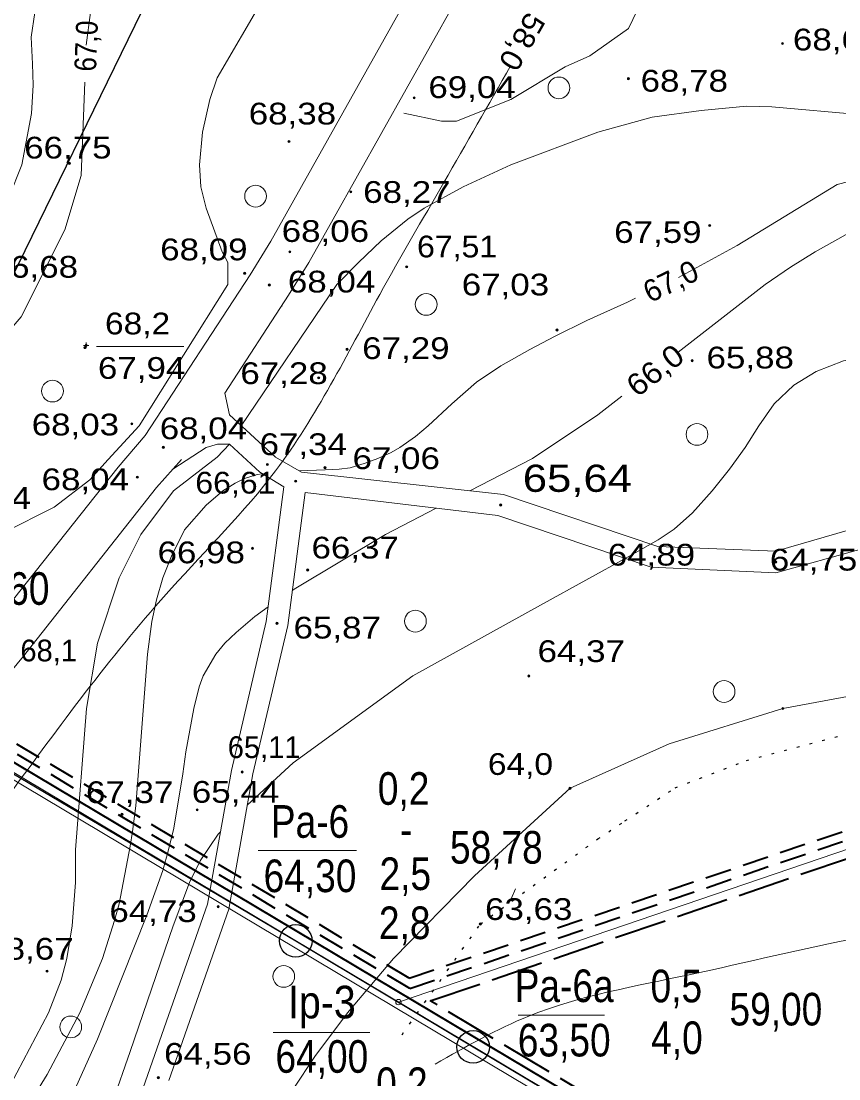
# Model space of a CAD drawing. Extents: x 628176 to 629009, y 6439913 to 6440496.
# Drawn here: x 628286 to 628361.2, y 6440164.9 to 6440262.2 of the extents above; entities that cross this region are included whole.
import ezdxf
from ezdxf.enums import TextEntityAlignment as Align

# ---------------------------------------------------------------- set-up
doc = ezdxf.new("R2010")
doc.units = 0
doc.header["$LTSCALE"] = 0.8
for name, pattern in [('DOTTED', [1.5, 0.3, -1.2]), ('LONG_DASHED', [7.5, 6, -1.5]), ('MEDIUM_DASHED', [4.5, 3, -1.5])]:
    doc.linetypes.add(name, pattern=pattern)
for name, color, linetype, lineweight in [('1', 7, 'Continuous', 13), ('11', 7, 'Continuous', 13), ('12', 7, 'Continuous', 13), ('14', 7, 'Continuous', 25), ('16', 7, 'Continuous', 13), ('21', 7, 'MEDIUM_DASHED', 35), ('3', 7, 'Continuous', 13), ('6', 7, 'Continuous', 13)]:
    doc.layers.add(name, color=color, linetype=linetype, lineweight=lineweight)

msp = doc.modelspace()

# ---------------------------------------------------------------- hatches: boundary and pattern name
at = {"layer": '1'}
for points in [[(628356.0743, 6440260.1483, 1), (628355.8743, 6440260.1483, 1)], [(628341.9107, 6440256.9194, 1), (628341.7107, 6440256.9194, 1)], [(628322.2211, 6440255.1543, 1), (628322.0211, 6440255.1543, 1)], [(628310.7102, 6440251.1349, 1), (628310.5102, 6440251.1349, 1)], [(628290.5201, 6440249.1263, 1), (628290.3201, 6440249.1263, 1)], [(628316.3947, 6440246.5031, 1), (628316.1947, 6440246.5031, 1)], [(628349.3792, 6440243.4059, 1), (628349.1792, 6440243.4059, 1)], [(628310.7867, 6440240.9912, 1), (628310.5867, 6440240.9912, 1)], [(628321.5289, 6440239.6149, 1), (628321.3289, 6440239.6149, 1)], [(628306.6381, 6440239.022, 1), (628306.4381, 6440239.022, 1)], [(628308.9023, 6440237.9449, 1), (628308.7023, 6440237.9449, 1)], [(628335.3481, 6440233.8017, 1), (628335.1481, 6440233.8017, 1)], [(628291.9429, 6440232.1859, 1), (628291.7429, 6440232.1859, 1)], [(628292.0618, 6440232.3913, 1), (628291.8618, 6440232.3913, 1)], [(628316.0509, 6440232.031, 1), (628315.8509, 6440232.031, 1)], [(628347.7719, 6440230.9816, 1), (628347.5719, 6440230.9816, 1)], [(628313.4424, 6440229.4082, 1), (628313.2424, 6440229.4082, 1)], [(628296.2665, 6440225.1736, 1), (628296.0665, 6440225.1736, 1)], [(628299.1586, 6440223.008, 1), (628298.9586, 6440223.008, 1)], [(628308.7274, 6440221.4346, 1), (628308.5274, 6440221.4346, 1)], [(628314.015, 6440221.1369, 1), (628313.815, 6440221.1369, 1)], [(628296.7687, 6440220.2651, 1), (628296.5687, 6440220.2651, 1)], [(628311.3292, 6440219.9008, 1), (628311.1292, 6440219.9008, 1)], [(628330.1709, 6440217.705, 1), (628329.9709, 6440217.705, 1)], [(628307.3536, 6440213.7223, 1), (628307.1536, 6440213.7223, 1)], [(628344.3043, 6440212.9299, 1), (628344.1043, 6440212.9299, 1)], [(628355.4645, 6440212.4726, 1), (628355.2645, 6440212.4726, 1)], [(628312.433, 6440211.7256, 1), (628312.233, 6440211.7256, 1)], [(628309.6075, 6440206.8223, 1), (628309.4075, 6440206.8223, 1)], [(628332.7532, 6440201.9901, 1), (628332.5532, 6440201.9901, 1)], [(628356.0999, 6440198.9999, 1), (628355.8999, 6440198.9999, 1)], [(628306.4084, 6440193.1498, 1), (628306.2084, 6440193.1498, 1)], [(628336.5375, 6440191.6623, 1), (628336.3375, 6440191.6623, 1)], [(628295.359, 6440189.2608, 1), (628295.159, 6440189.2608, 1)], [(628302.2659, 6440189.6821, 1), (628302.0659, 6440189.6821, 1)], [(628304.2013, 6440180.7755, 1), (628304.0013, 6440180.7755, 1)], [(628328.2942, 6440179.1745, 1), (628328.0942, 6440179.1745, 1)], [(628288.4747, 6440174.84, 1), (628288.2747, 6440174.84, 1)], [(628298.6987, 6440165.0565, 1), (628298.4987, 6440165.0565, 1)]]:
    msp.add_hatch(color=256, dxfattribs=at).paths.add_polyline_path(points)

# ---------------------------------------------------------------- linework, layer by layer
for p, q in [((628308.95, 6440241.98), (628322.23, 6440265.66)), ((628312.42, 6440240), (628325.84, 6440263.93)), ((628307.03, 6440238.88), (628308.95, 6440241.98)), ((628310.56, 6440237), (628312.42, 6440240)), ((628297.39, 6440224.11), (628307.03, 6440238.88)), ((628304.7, 6440228), (628310.56, 6440237)), ((628291.96, 6440232.39), (628291.71, 6440232.39)), ((628291.96, 6440232.39), (628291.96, 6440232.64)), ((628291.96, 6440232.39), (628292.21, 6440232.39)), ((628291.96, 6440232.39), (628291.96, 6440232.14)), ((628300.93, 6440232.27), (628292.93, 6440232.27)), ((628305.13, 6440226), (628304.7, 6440228)), ((628309.36, 6440222.11), (628305.13, 6440226)), ((628294.9, 6440221.2), (628297.39, 6440224.11)), ((628307.93, 6440220.72), (628305.13, 6440223.29)), ((628311.77, 6440220.74), (628309.36, 6440222.11)), ((628282.81, 6440205.93), (628294.9, 6440221.2)), ((628298.44, 6440219.33), (628300.73, 6440221.9)), ((628310.15, 6440219.38), (628307.93, 6440220.72)), ((628330.33, 6440218.67), (628311.77, 6440220.74)), ((628286.21, 6440203.81), (628298.44, 6440219.33)), ((628308.52, 6440207), (628310.15, 6440219.38)), ((628310.49, 6440206.64), (628312.09, 6440218.85)), ((628329.82, 6440216.74), (628312.09, 6440218.85)), ((628344.5, 6440213.88), (628330.33, 6440218.67)), ((628343.9, 6440211.98), (628329.82, 6440216.74)), ((628364, 6440215.96), (628355.36, 6440213.47)), ((628355.36, 6440213.47), (628344.5, 6440213.88)), ((628364.35, 6440213.99), (628355.36, 6440211.47)), ((628355.36, 6440211.47), (628343.9, 6440211.98)), ((628305.32, 6440193.3), (628308.52, 6440207)), ((628307.3, 6440193), (628310.49, 6440206.64)), ((628269.01, 6440183.06), (628286.21, 6440203.81)), ((628303.13, 6440181), (628305.32, 6440193.3)), ((628305.08, 6440180.55), (628307.3, 6440193)), ((628297.64, 6440165.34), (628303.13, 6440181)), ((628299.56, 6440164.78), (628305.08, 6440180.55)), ((628286.97, 6440135.42), (628297.64, 6440165.34))]:
    msp.add_line(p, q, dxfattribs=at)
msp.add_lwpolyline([(628305.13, 6440223.29), (628304.04, 6440223.29), (628303, 6440223), (628299.92, 6440221)], dxfattribs=at)
at = {"layer": '1', "linetype": 'DOTTED', "lineweight": 25}
for points in [[(628339, 6440187), (628341.49, 6440188.66), (628346.11, 6440191.7), (628352.66, 6440194.21), (628361.18, 6440196.45)], [(628321, 6440169), (628328.19, 6440179.17), (628339, 6440187)]]:
    msp.add_lwpolyline(points, dxfattribs=at)
at = {"layer": '1'}
for centre, radius in [((628355.9743, 6440260.1483), 0.1), ((628335.4179, 6440256.0666), 1), ((628341.8107, 6440256.9194), 0.1), ((628322.1211, 6440255.1543), 0.1), ((628310.6102, 6440251.1349), 0.1), ((628290.4201, 6440249.1263), 0.1), ((628307.5389, 6440246.1098), 1), ((628316.2947, 6440246.5031), 0.1), ((628349.2792, 6440243.4059), 0.1), ((628310.6867, 6440240.9912), 0.1), ((628321.4289, 6440239.6149), 0.1), ((628306.5381, 6440239.022), 0.1), ((628308.8023, 6440237.9449), 0.1), ((628323.2209, 6440236.1531), 1), ((628335.2481, 6440233.8017), 0.1), ((628291.8429, 6440232.1859), 0.1), ((628291.9618, 6440232.3913), 0.1), ((628315.9509, 6440232.031), 0.1), ((628347.6719, 6440230.9816), 0.1), ((628288.87, 6440228.1876), 1), ((628313.3424, 6440229.4082), 0.1), ((628296.1665, 6440225.1736), 0.1), ((628348.1128, 6440224.2049), 1), ((628299.0586, 6440223.008), 0.1), ((628308.6274, 6440221.4346), 0.1), ((628313.915, 6440221.1369), 0.1), ((628296.6687, 6440220.2651), 0.1), ((628311.2292, 6440219.9008), 0.1), ((628330.0709, 6440217.705), 0.1), ((628307.2536, 6440213.7223), 0.1), ((628344.2043, 6440212.9299), 0.1), ((628355.3645, 6440212.4726), 0.1), ((628312.333, 6440211.7256), 0.1), ((628322.2252, 6440207.0295), 1), ((628309.5075, 6440206.8223), 0.1), ((628332.6532, 6440201.9901), 0.1), ((628350.602, 6440200.5576), 1), ((628355.9999, 6440198.9999), 0.1), ((628306.3084, 6440193.1498), 0.1), ((628336.4375, 6440191.6623), 0.1), ((628295.259, 6440189.2608), 0.1), ((628302.1659, 6440189.6821), 0.1), ((628304.1013, 6440180.7755), 0.1), ((628328.1942, 6440179.1745), 0.1), ((628310.1267, 6440174.3603), 1), ((628288.3747, 6440174.84), 0.1), ((628290.5482, 6440169.7104), 1), ((628298.5987, 6440165.0565), 0.1)]:
    msp.add_circle(centre, radius, dxfattribs=at)
at = {"layer": '11'}
for points in [[(628497.5, 6440118.54), (628474.19, 6440080.39), (628272.25, 6440200.89), (628236.02, 6440221.83), (628393.19, 6440398.39)], [(628320.67, 6440172), (628398.18, 6440198.42), (628472.21, 6440157.1), (628497.5, 6440118.54)]]:
    msp.add_lwpolyline(points, dxfattribs=at)
at = {"layer": '12'}
for p, q in [((628307.79, 6440185.95), (628316.83, 6440185.95)), ((628331.66, 6440170.81), (628339.61, 6440170.81)), ((628309.16, 6440169.2), (628318.03, 6440169.2))]:
    msp.add_line(p, q, dxfattribs=at)
at = {"layer": '12', "lineweight": 25}
for centre in [(628311.2274, 6440177.6315), (628327.5332, 6440167.8785)]:
    msp.add_circle(centre, 1.5, dxfattribs=at)
at = {"layer": '12'}
msp.add_circle((628320.6692, 6440171.9974), 0.25, dxfattribs=at)
at = {"layer": '14'}
msp.add_line((628326.62, 6440323.6), (628267.86, 6440203.3), dxfattribs=at)
msp.add_lwpolyline([(628267.86, 6440203.3), (628311.23, 6440177.63), (628327.53, 6440167.88), (628373.06, 6440140.73), (628474.19, 6440080.39), (628476.16, 6440079.17)], dxfattribs=at)
at = {"layer": '16'}
msp.add_line((628331.42, 6440182.41), (628331.04, 6440181.48), dxfattribs=at)
for points in [[(628330.97, 6440258.09), (628324.85, 6440247.37), (628318.95, 6440237.06), (628309.38, 6440220.86), (628299.81, 6440210.06), (628285.32, 6440191.65)], [(628369.28, 6440179.01), (628363.18, 6440177.96), (628347.39, 6440174.51), (628332.71, 6440170.73), (628324.04, 6440166.29)]]:
    msp.add_spline(points, degree=3, dxfattribs=at)
at = {"layer": '21', "linetype": 'Continuous', "lineweight": 40}
for points in [[(628320.39, 6440173.09), (628272.66, 6440201.58), (628237.27, 6440222.03), (628393.6, 6440397.65)], [(628496.82, 6440118.96), (628473.92, 6440081.48), (628320.39, 6440173.09)]]:
    msp.add_lwpolyline(points, dxfattribs=at)
at = {"layer": '21'}
for points in [[(628321.72, 6440173.24), (628273.06, 6440202.27), (628238.52, 6440222.23), (628394.01, 6440396.91)], [(628321.66, 6440174.2), (628273.47, 6440202.96), (628239.77, 6440222.44), (628394.43, 6440396.17)], [(628321.66, 6440174.2), (628398.34, 6440200.16), (628470.2, 6440160.05)], [(628321.72, 6440173.24), (628398.26, 6440199.29), (628472.77, 6440157.71), (628496.99, 6440120.78)]]:
    msp.add_lwpolyline(points, dxfattribs=at)
at = {"layer": '21', "linetype": 'LONG_DASHED'}
for points in [[(628323.6, 6440172.11), (628398.09, 6440197.56), (628471.64, 6440156.5), (628496.07, 6440119.27)], [(628496.07, 6440119.27), (628473.65, 6440082.57), (628323.6, 6440172.11)]]:
    msp.add_lwpolyline(points, dxfattribs=at)
at = {"layer": '3'}
for p, q in [((628336, 6440258), (628338.27, 6440259)), ((628287.08, 6440256.31), (628287.02, 6440258.27)), ((628287.08, 6440256.31), (628286.94, 6440253.71)), ((628291.5, 6440248), (628291.83, 6440256.58)), ((628355, 6440254.32), (628352.65, 6440254.39)), ((628355, 6440254.32), (628363.65, 6440253.56)), ((628286.06, 6440249), (628286.94, 6440253.71)), ((628286.06, 6440249), (628284.87, 6440246)), ((628303, 6440245), (628302.52, 6440246.98)), ((628303, 6440245), (628304.48, 6440241)), ((628351.82, 6440241.56), (628346.42, 6440238.64)), ((628304.48, 6440241), (628304.99, 6440240)), ((628315, 6440238), (628317, 6440240)), ((628315, 6440238), (628306.22, 6440225)), ((628346.37, 6440231.75), (628354.39, 6440238)), ((628342.46, 6440236.73), (628341.71, 6440236.37)), ((628309.93, 6440236.02), (628309.99, 6440236)), ((628341.71, 6440236.37), (628338, 6440234.69)), ((628339, 6440226), (628341.21, 6440227.73)), ((628333, 6440222), (628339, 6440226)), ((628296.85, 6440225), (628294, 6440221.9)), ((628318.78, 6440222), (628320, 6440222.54)), ((628317.6, 6440221.56), (628316.23, 6440221.14)), ((628318.78, 6440222), (628317.6, 6440221.56)), ((628327.24, 6440219.02), (628333, 6440222)), ((628313.92, 6440220.93), (628311.56, 6440220.86)), ((628301, 6440215.43), (628303, 6440217.68)), ((628319.48, 6440215), (628324.14, 6440217.41)), ((628346, 6440215.5), (628345.29, 6440215)), ((628319.48, 6440215), (628311.23, 6440210.06)), ((628344.53, 6440214.51), (628341.8, 6440212.93)), ((628345.29, 6440215), (628344.53, 6440214.51)), ((628341.8, 6440212.93), (628334, 6440208.66)), ((628311.23, 6440210.06), (628310.91, 6440209.85)), ((628307.48, 6440207.47), (628305.74, 6440206)), ((628308.7, 6440208.34), (628307.48, 6440207.47)), ((628302.72, 6440202), (628302.35, 6440201)), ((628300.84, 6440193), (628300.03, 6440188)), ((628304.32, 6440187.66), (628304.1, 6440187.44)), ((628299, 6440184.09), (628297.55, 6440180)), ((628297.55, 6440180), (628293, 6440168.58)), ((628293, 6440168.58), (628289.4, 6440160.56)), ((628296, 6440167.47), (628283.77, 6440131.85))]:
    msp.add_line(p, q, dxfattribs=at)
for points in [[(628351.82, 6440241.56), (628361, 6440247.17), (628368, 6440249), (628373.51, 6440249), (628378, 6440248), (628381, 6440248), (628383, 6440250), (628385, 6440255), (628389, 6440258), (628395, 6440263), (628394.03, 6440267), (628390, 6440273), (628389, 6440277), (628390, 6440281), (628395, 6440287), (628400, 6440291)], [(628303.32, 6440255), (628304, 6440257), (628308.28, 6440264.32), (628311, 6440269), (628312, 6440272), (628312.51, 6440275), (628313, 6440289)], [(628338.27, 6440259), (628341.81, 6440261.52), (628343, 6440264), (628341.81, 6440270), (628341, 6440275)], [(628291.96, 6440260), (628292.36, 6440263), (628294, 6440269)], [(628289, 6440266.65), (628288, 6440265), (628287.25, 6440263), (628286.9, 6440260.74), (628287.02, 6440258.27)], [(628336, 6440258), (628331, 6440255), (628326, 6440253), (628324.63, 6440253), (628321.17, 6440253.75)], [(628303.32, 6440255), (628302.66, 6440252), (628302.38, 6440249), (628302.52, 6440246.98)], [(628344, 6440253.38), (628348.5, 6440254), (628352.65, 6440254.39)], [(628344, 6440253.38), (628339, 6440252), (628331, 6440249)], [(628331, 6440249), (628326.62, 6440246.98), (628323.04, 6440245), (628321.53, 6440244), (628319.07, 6440242), (628317, 6440240)], [(628291.5, 6440248), (628290, 6440243), (628286, 6440235), (628283.4, 6440232)], [(628354.39, 6440238), (628356.7, 6440239.57), (628358.98, 6440241), (628362.6, 6440243)], [(628304.99, 6440240), (628304.99, 6440238), (628296.85, 6440225)], [(628332.74, 6440232), (628335, 6440233.2), (628338, 6440234.69)], [(628332.74, 6440232), (628330.07, 6440230.51), (628327.86, 6440229), (628325.57, 6440227), (628323.41, 6440225), (628322.25, 6440224), (628320.8, 6440223), (628320, 6440222.54)], [(628363.66, 6440231.43), (628361.57, 6440230.98), (628359.07, 6440230), (628357, 6440228.72), (628355.2, 6440227), (628353.8, 6440225), (628352.53, 6440223), (628351.1, 6440221)], [(628291, 6440186), (628292, 6440199), (628293, 6440205), (628295, 6440211), (628297, 6440215), (628300, 6440219), (628304, 6440222.11), (628305.13, 6440223.29)], [(628247.36, 6440198), (628250.26, 6440199.16), (628254.18, 6440200.71), (628258.01, 6440202.29), (628260.57, 6440203.93), (628263.92, 6440205.56), (628266.12, 6440206.84), (628269.18, 6440208.41), (628273.81, 6440210.62), (628278, 6440212.18), (628280.26, 6440213.27), (628284.41, 6440215.17), (628289.01, 6440217.52), (628292.3, 6440220.03), (628294, 6440221.9)], [(628316.23, 6440221.14), (628315.22, 6440221), (628313.92, 6440220.93)], [(628308.14, 6440220.59), (628307.67, 6440220.51), (628306.6, 6440220.17), (628305.66, 6440219.73), (628304.53, 6440219), (628303, 6440217.68)], [(628351.1, 6440221), (628349.52, 6440219), (628347.71, 6440217), (628346, 6440215.5)], [(628301, 6440215.43), (628299.8, 6440213), (628299, 6440211), (628298.44, 6440209), (628298.01, 6440207), (628297.6, 6440204), (628296.53, 6440190.04), (628296.24, 6440187.7), (628296, 6440186.33), (628295, 6440181.04), (628294.58, 6440179.51), (628293.46, 6440176), (628291.38, 6440171), (628288.37, 6440165.35), (628282, 6440155), (628274, 6440141)], [(628334, 6440208.66), (628322, 6440201.99), (628311, 6440194), (628306.78, 6440190.12)], [(628305.74, 6440206), (628304.72, 6440205), (628303.89, 6440204), (628302.72, 6440202)], [(628356, 6440199), (628366.09, 6440200.87), (628376, 6440202)], [(628302.35, 6440201), (628301.86, 6440199), (628301.14, 6440195), (628300.84, 6440193)], [(628336.44, 6440191.66), (628345.57, 6440195.74), (628356, 6440199)], [(628320.21, 6440176), (628327.66, 6440183.62), (628336.44, 6440191.66)], [(628300.03, 6440188), (628299.54, 6440186), (628299, 6440184.09)], [(628304.1, 6440187.44), (628302.44, 6440185), (628301.45, 6440183)], [(628291, 6440186), (628291, 6440183), (628290.67, 6440179), (628290.19, 6440176), (628289.67, 6440174), (628288.49, 6440171), (628285, 6440164.4), (628277, 6440153), (628270.83, 6440142.75)], [(628301.45, 6440183), (628299.96, 6440179), (628296, 6440167.47)], [(628320.21, 6440176), (628316, 6440171), (628313, 6440167), (628309, 6440161)]]:
    msp.add_lwpolyline(points, dxfattribs=at)
at = {"layer": '6'}
msp.add_lwpolyline([(628473.77, 6440079.94), (628271.95, 6440200.37), (628235.6, 6440221.38)], dxfattribs=at)

# ---------------------------------------------------------------- texts
at = {"layer": '1'}
for s, height, width, p in [('68,68', 2, 1.2, (628356.93, 6440259.51)), ('69,04', 2, 1.2, (628323.42, 6440255.13)), ('68,78', 2, 1.2, (628342.93, 6440255.72)), ('68,38', 2, 1.2, (628306.91, 6440252.7)), ('66,75', 2, 1.2, (628286.27, 6440249.57)), ('68,27', 2, 1.2, (628317.43, 6440245.49)), ('68,06', 2, 1.2, (628309.94, 6440241.9)), ('67,59', 2, 1.2, (628340.5, 6440241.81)), ('67,51', 2, 1.1, (628322.38, 6440240.48)), ('68,09', 2, 1.2, (628298.77, 6440240.21)), ('66,68', 2, 1.2, (628283.19, 6440238.61)), ('68,04', 2, 1.2, (628310.51, 6440237.25)), ('67,03', 2, 1.2, (628326.49, 6440236.98)), ('68,2', 2, 1.15, (628293.7, 6440233.4)), ('67,29', 2, 1.2, (628317.34, 6440231.13)), ('65,88', 2, 1.2, (628348.99, 6440230.27)), ('67,94', 2, 1.2, (628293.05, 6440229.31)), ('67,28', 2, 1.2, (628306.14, 6440228.83)), ('68,03', 2, 1.2, (628286.96, 6440224.11)), ('68,04', 2, 1.2, (628298.73, 6440223.76)), ('67,34', 2, 1.2, (628307.91, 6440222.3)), ('67,06', 2, 1.2, (628316.45, 6440221.01)), ('68,04', 2, 1.2, (628287.87, 6440219.07)), ('65,64', 2.5, 1.2, (628332.1, 6440218.92)), ('66,61', 2, 1.1, (628302, 6440218.76)), ('67,64', 2, 1.2, (628278.86, 6440217.35)), ('66,98', 2, 1.2, (628298.53, 6440212.35)), ('66,37', 2, 1.2, (628312.68, 6440212.79)), ('64,89', 2, 1.2, (628339.91, 6440212.14)), ('64,75', 2, 1.2, (628354.81, 6440211.68)), ('65,87', 2, 1.2, (628311.03, 6440205.43)), ('64,37', 2, 1.2, (628333.46, 6440203.27)), ('64,0', 2, 1.15, (628328.89, 6440192.89)), ('67,37', 2, 1.2, (628291.95, 6440190.3)), ('65,44', 2, 1.2, (628301.68, 6440190.33)), ('64,73', 2, 1.2, (628294.1, 6440179.36)), ('63,63', 2, 1.2, (628328.63, 6440179.55)), ('68,67', 2, 1.2, (628282.78, 6440175.9)), ('64,56', 2, 1.2, (628299.13, 6440166.24))]:
    msp.add_text(s, height=height, dxfattribs=dict(at, width=width)).set_placement(p)
for s, p in [('68,1', (628285.92, 6440203.33)), ('65,11', (628304.98, 6440194.44))]:
    msp.add_text(s, height=2, dxfattribs=at).set_placement(p)
at = {"layer": '11', "width": 0.85}
for s, p in [('0,2', (628321.145, 6440190.14)), ('0,5', (628346.215, 6440171.98)), ('0,2', (628320.99, 6440162.99))]:
    msp.add_text(s, height=3, dxfattribs=at).set_placement(p, align=Align.CENTER)
at = {"layer": '12'}
for s, width, p in [('57,60', 0.85, (628284.325, 6440208.53)), ('Pa-6', 0.85, (628312.54, 6440187.11)), ('-', 0.85, (628321.39, 6440186.37)), ('58,78', 0.85, (628329.67, 6440184.73)), ('64,30', 0.85, (628312.54, 6440182.11)), ('2,5', 0.85, (628321.3, 6440182.3)), ('2,8', 0.85, (628321.245, 6440177.79)), ('Pa-6a', 0.85, (628335.905, 6440172)), ('Ip-3', 0.9, (628313.63, 6440170.5)), ('59,00', 0.85, (628355.365, 6440169.85)), ('63,50', 0.85, (628335.91, 6440167)), ('4,0', 0.85, (628346.27, 6440167.22)), ('64,00', 0.85, (628313.63, 6440165.5))]:
    msp.add_text(s, height=3, dxfattribs=dict(at, width=width)).set_placement(p, align=Align.CENTER)
at = {"layer": '16', "width": 1.05}
msp.add_text('58,0', height=2, rotation=240.255, dxfattribs=at).set_placement((628331.1635, 6440260.8011), align=Align.CENTER)
at = {"layer": '3'}
for s, rotation, width, p in [('67,0', 87.796, 0.9, (628292.87, 6440257.54)), ('66,0', 37.947, 1.1, (628342.62, 6440227.55))]:
    msp.add_text(s, height=2, rotation=rotation, dxfattribs=dict(at, width=width)).set_placement(p)
msp.add_text('67,0', height=2, rotation=25.769, dxfattribs=at).set_placement((628343.79, 6440236.26))

doc.saveas('drawing.dxf')
